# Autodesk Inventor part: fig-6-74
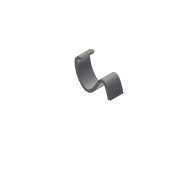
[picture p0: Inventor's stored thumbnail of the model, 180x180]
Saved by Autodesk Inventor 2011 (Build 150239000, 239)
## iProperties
Shininess: 64.0
Length Units: 11269
Angle Units: 11279
Time Units: 11290
Mass Units: 11283
Length Display Precision: 3
Angle Display Precision: 2
Compacted: True
Part Number: fig-6-74
Document SubType Name: Modeling
Created: 2002-12
Designer: deepak
Density: 1 g/cm^3
Density: 0.0
Volumn: 0.0
Area: 0.0
PropertySet Name: Model Information
Control State: 0
Master: False
Checked Out: False
Author: deepak
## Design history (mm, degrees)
sketch "Sketch1"
  geometry: 5 further points
  constraints: 5 other
extrude_surface "ExtrusionSrf1" sketch "Sketch1" dims "d0" = 20, "d1" = 0
thicken "Thicken2" dims "d6" = 4, "d7" = 4
body "Solid1"
body "Srf1"
